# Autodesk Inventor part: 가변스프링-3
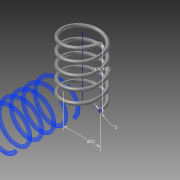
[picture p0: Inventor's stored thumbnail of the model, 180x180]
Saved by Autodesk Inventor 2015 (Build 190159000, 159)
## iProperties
Created: 2016-01
Part Number: 가변스프링-3
Material: 스테인레스 스틸
Document SubType Name: Modeling
Designer: 601-23
Density: 8 g/cm^3
Appearance: 반연마
Mass: 8.58443 g
Surface Area: 21.7229 cm^2
Volume: 1.07305 cm^3
Author: 601-23
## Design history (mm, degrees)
sketch "스케치1"
  geometry: L1 (0, 0)-(11, 0); L2 (11, 0)-(11, 36.411); L3 (11, 36.411)-(0, 36.411); L4 (0, 36.411)-(0, 0); C1 r 1 at (11, 0)
  constraints: 8 end point, 2 parallel, 1 centre point, 1 coincident, 1 horizontal, 1 perpendicular
  dimensions: "d0" = 36.4112 distance of L1.end L2.end (derived); "d1" = 22 diameter of L2 L4; "d2" = 2 diameter of C1
feature "코일1" sketch "스케치1" pitch "d3" = 5; turns "d5" = 5; dims "d4" = 36.4112 (= d0), "d6" = 0, angle "d7" = 90 deg, angle "d8" = 90 deg, "d9" = 0, "d10" = 0
node "작업 평면1"
node "작업 평면2"
sketch "스케치2"
  geometry: L1 (1, 0)-(-1, 0) reference; 1 further point
  constraints: 1 horizontal alignment
extrude "돌출1" cut sketch "스케치2" stored distance "d13" = 10; taper "d14" = 0 deg
sketch "스케치3"
  geometry: L1 (10, 0)-(12, 0) reference; 1 further point
  constraints: 1 horizontal alignment
extrude "돌출2" cut sketch "스케치3" stored distance "d15" = 10; taper "d16" = 0 deg
node "솔리드1"
node "절단 모서리 투영1"
node "절단 모서리 투영2"
other parameters: "d11" = 90 deg, "d12" = 90 deg
